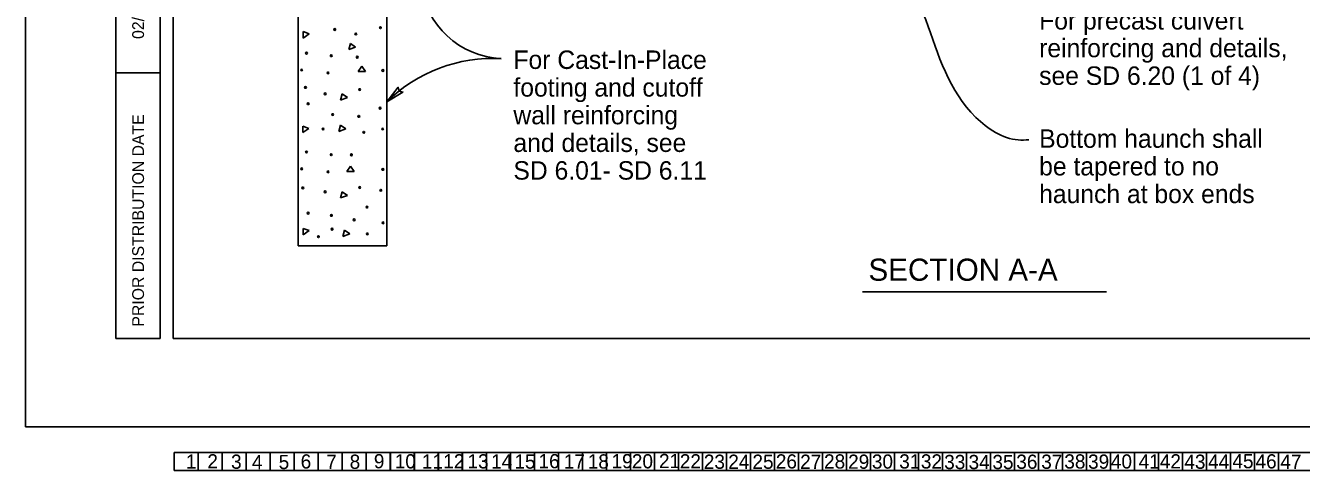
# Model space of a CAD drawing. Extents: x 0 to 2.83, y -0.03 to 1.83.
# Drawn here: x 0 to 0.9, y -0.031 to 0.283 of the extents above; entities that cross this region are included whole.
import ezdxf

# ---------------------------------------------------------------- set-up
doc = ezdxf.new("R2010")
doc.units = 0
for name, color, linetype in [('1', 7, 'Continuous'), ('10', 7, 'Continuous'), ('11', 7, 'Continuous'), ('12', 7, 'Continuous'), ('13', 7, 'Continuous'), ('14', 7, 'Continuous'), ('15', 7, 'Continuous'), ('16', 7, 'Continuous'), ('17', 7, 'Continuous'), ('18', 7, 'Continuous'), ('19', 7, 'Continuous'), ('2', 7, 'Continuous'), ('20', 7, 'Continuous'), ('21', 7, 'Continuous'), ('22', 7, 'Continuous'), ('23', 7, 'Continuous'), ('24', 7, 'Continuous'), ('25', 7, 'Continuous'), ('26', 7, 'Continuous'), ('27', 7, 'Continuous'), ('28', 7, 'Continuous'), ('29', 7, 'Continuous'), ('3', 7, 'Continuous'), ('30', 7, 'Continuous'), ('31', 7, 'Continuous'), ('32', 7, 'Continuous'), ('33', 7, 'Continuous'), ('34', 7, 'Continuous'), ('35', 7, 'Continuous'), ('36', 7, 'Continuous'), ('37', 7, 'Continuous'), ('38', 7, 'Continuous'), ('39', 7, 'Continuous'), ('4', 7, 'Continuous'), ('40', 7, 'Continuous'), ('41', 7, 'Continuous'), ('42', 7, 'Continuous'), ('43', 7, 'Continuous'), ('44', 7, 'Continuous'), ('45', 7, 'Continuous'), ('46', 7, 'Continuous'), ('47', 7, 'Continuous'), ('5', 7, 'Continuous'), ('50', 7, 'Continuous'), ('54', 7, 'Continuous'), ('55', 7, 'Continuous'), ('57', 7, 'Continuous'), ('6', 7, 'Continuous'), ('62', 7, 'Continuous'), ('63', 7, 'Continuous'), ('7', 7, 'Continuous'), ('8', 7, 'Continuous'), ('9', 7, 'Continuous')]:
    doc.layers.add(name, color=color, linetype=linetype)

msp = doc.modelspace()

# ---------------------------------------------------------------- linework, layer by layer
at = {"layer": '50'}
for p, q in [((0.19238, 0.1279), (0.19238, 0.37139)), ((0.25488, 0.1279), (0.25488, 0.31279)), ((0.19589, 0.2745), (0.19587, 0.27906)), ((0.19587, 0.27906), (0.20015, 0.27749)), ((0.20015, 0.27749), (0.19589, 0.2745)), ((0.22799, 0.26628), (0.22915, 0.27068)), ((0.22915, 0.27068), (0.23289, 0.26805)), ((0.23289, 0.26805), (0.22799, 0.26628)), ((0.23462, 0.25087), (0.23722, 0.25461)), ((0.23722, 0.25461), (0.23983, 0.25087)), ((0.23983, 0.25087), (0.23462, 0.25087)), ((0.2223, 0.23071), (0.22347, 0.23511)), ((0.22347, 0.23511), (0.2272, 0.23248)), ((0.2272, 0.23248), (0.2223, 0.23071)), ((0.19563, 0.20772), (0.19562, 0.21228)), ((0.19562, 0.21228), (0.1999, 0.21071)), ((0.1999, 0.21071), (0.19563, 0.20772)), ((0.22096, 0.2085), (0.22213, 0.2129)), ((0.22586, 0.21028), (0.22096, 0.2085)), ((0.22213, 0.2129), (0.22586, 0.21028)), ((0.22666, 0.18037), (0.22926, 0.18412)), ((0.23187, 0.18037), (0.22666, 0.18037)), ((0.22926, 0.18412), (0.23187, 0.18037)), ((0.2223, 0.16156), (0.22347, 0.16596)), ((0.2272, 0.16334), (0.2223, 0.16156)), ((0.22347, 0.16596), (0.2272, 0.16334)), ((0.19589, 0.13555), (0.19587, 0.14011)), ((0.19587, 0.14011), (0.20015, 0.13853)), ((0.20015, 0.13853), (0.19589, 0.13555)), ((0.22384, 0.13442), (0.22501, 0.13882)), ((0.22874, 0.13619), (0.22384, 0.13442)), ((0.22501, 0.13882), (0.22874, 0.13619)), ((0.19238, 0.1279), (0.25488, 0.1279))]:
    msp.add_line(p, q, dxfattribs=at)
for centre in [(0.21815, 0.28053), (0.25037, 0.28178), (0.23299, 0.27734), (0.19824, 0.26382), (0.21569, 0.26196), (0.23404, 0.26094), (0.19479, 0.25193), (0.2521, 0.25155), (0.21337, 0.24986), (0.19748, 0.23961), (0.21136, 0.2351), (0.23572, 0.2381), (0.1994, 0.2281), (0.25014, 0.22501), (0.21668, 0.22044), (0.23512, 0.21918), (0.20991, 0.21025), (0.23864, 0.20791), (0.25196, 0.21029), (0.19824, 0.19401), (0.21569, 0.19215), (0.2299, 0.19201), (0.19479, 0.18212), (0.21337, 0.18004), (0.2521, 0.18174), (0.1956, 0.16869), (0.21136, 0.16595), (0.23572, 0.16896), (0.25065, 0.16699), (0.24092, 0.15517), (0.1994, 0.15088), (0.21578, 0.14926), (0.23184, 0.14618), (0.25217, 0.14403), (0.21628, 0.13957), (0.24114, 0.13618), (0.20662, 0.13428)]:
    msp.add_circle(centre, 0.000626, dxfattribs=at)
at = {"layer": '54'}
msp.add_lwpolyline([(0.25488, 0.22946), (0.26618, 0.2363), (0.26347, 0.23707), (0.2629, 0.23977)], close=True, dxfattribs=at)
at = {"layer": '55'}
for centre, radius, start, end in [((0.33842, 0.31981), 0.05996, 186.7254, 267.33645), ((0.3295, 0.15391), 0.10619, 86.68773, 134.64958)]:
    msp.add_arc(centre, radius, start, end, dxfattribs=at)
msp.add_spline([(0.70782, 0.20258), (0.70033, 0.20258), (0.67037, 0.21846), (0.63506, 0.28728), (0.6158, 0.33281), (0.59119, 0.36775), (0.57514, 0.37939), (0.56016, 0.38469), (0.4949, 0.38786), (0.31393, 0.39457)], degree=3, dxfattribs=at)
at = {"layer": '57'}
msp.add_line((0.59055, 0.09532), (0.76264, 0.09532), dxfattribs=at)
at = {"layer": '62'}
for p, q in [((0.10494, -0.01804), (0.10494, -0.03074)), ((0.10494, -0.01804), (1.17174, -0.01804)), ((0.10496, -0.0181), (0.10496, -0.0308)), ((0.10496, -0.0181), (1.17175, -0.0181)), ((0.12188, -0.01804), (0.12188, -0.03074)), ((0.12189, -0.0181), (0.12189, -0.0308)), ((0.13881, -0.01804), (0.13881, -0.03074)), ((0.13882, -0.0181), (0.13882, -0.0308)), ((0.15574, -0.01804), (0.15574, -0.03074)), ((0.15576, -0.0181), (0.15576, -0.0308)), ((0.17267, -0.01804), (0.17267, -0.03074)), ((0.17269, -0.0181), (0.17269, -0.0308)), ((0.18961, -0.01804), (0.18961, -0.03074)), ((0.18962, -0.0181), (0.18962, -0.0308)), ((0.20654, -0.01804), (0.20654, -0.03074)), ((0.20656, -0.0181), (0.20656, -0.0308)), ((0.22348, -0.01804), (0.22348, -0.03074)), ((0.22349, -0.0181), (0.22349, -0.0308)), ((0.24041, -0.01804), (0.24041, -0.03074)), ((0.24042, -0.0181), (0.24042, -0.0308)), ((0.25734, -0.01804), (0.25734, -0.03074)), ((0.25736, -0.0181), (0.25736, -0.0308)), ((0.27427, -0.01804), (0.27427, -0.03074)), ((0.27429, -0.0181), (0.27429, -0.0308)), ((0.29121, -0.01804), (0.29121, -0.03074)), ((0.29122, -0.0181), (0.29122, -0.0308)), ((0.30814, -0.01804), (0.30814, -0.03074)), ((0.30816, -0.0181), (0.30816, -0.0308)), ((0.32508, -0.01804), (0.32508, -0.03074)), ((0.32509, -0.0181), (0.32509, -0.0308)), ((0.34201, -0.01804), (0.34201, -0.03074)), ((0.34202, -0.0181), (0.34202, -0.0308)), ((0.35894, -0.01804), (0.35894, -0.03074)), ((0.35896, -0.0181), (0.35896, -0.0308)), ((0.37588, -0.01804), (0.37588, -0.03074)), ((0.37589, -0.0181), (0.37589, -0.0308)), ((0.39281, -0.01804), (0.39281, -0.03074)), ((0.39282, -0.0181), (0.39282, -0.0308)), ((0.40974, -0.01804), (0.40974, -0.03074)), ((0.40976, -0.0181), (0.40976, -0.0308)), ((0.42668, -0.01804), (0.42668, -0.03074)), ((0.42669, -0.0181), (0.42669, -0.0308)), ((0.44361, -0.01804), (0.44361, -0.03074)), ((0.44362, -0.0181), (0.44362, -0.0308)), ((0.46054, -0.01804), (0.46054, -0.03074)), ((0.46056, -0.0181), (0.46056, -0.0308)), ((0.47748, -0.01804), (0.47748, -0.03074)), ((0.47749, -0.0181), (0.47749, -0.0308)), ((0.49441, -0.01804), (0.49441, -0.03074)), ((0.49442, -0.0181), (0.49442, -0.0308)), ((0.51134, -0.01804), (0.51134, -0.03074)), ((0.51136, -0.0181), (0.51136, -0.0308)), ((0.52828, -0.01804), (0.52828, -0.03074)), ((0.52829, -0.0181), (0.52829, -0.0308)), ((0.54521, -0.01804), (0.54521, -0.03074)), ((0.54522, -0.0181), (0.54522, -0.0308)), ((0.56214, -0.01804), (0.56214, -0.03074)), ((0.56216, -0.0181), (0.56216, -0.0308)), ((0.57908, -0.01804), (0.57908, -0.03074)), ((0.57909, -0.0181), (0.57909, -0.0308)), ((0.59601, -0.01804), (0.59601, -0.03074)), ((0.59602, -0.0181), (0.59602, -0.0308)), ((0.61294, -0.01804), (0.61294, -0.03074)), ((0.61296, -0.0181), (0.61296, -0.0308)), ((0.62988, -0.01804), (0.62988, -0.03074)), ((0.62989, -0.0181), (0.62989, -0.0308)), ((0.64681, -0.01804), (0.64681, -0.03074)), ((0.64682, -0.0181), (0.64682, -0.0308)), ((0.66374, -0.01804), (0.66374, -0.03074)), ((0.66376, -0.0181), (0.66376, -0.0308)), ((0.68068, -0.01804), (0.68068, -0.03074)), ((0.68069, -0.0181), (0.68069, -0.0308)), ((0.69761, -0.01804), (0.69761, -0.03074)), ((0.69762, -0.0181), (0.69762, -0.0308)), ((0.71454, -0.01804), (0.71454, -0.03074)), ((0.71456, -0.0181), (0.71456, -0.0308)), ((0.73147, -0.01804), (0.73147, -0.03074)), ((0.73149, -0.0181), (0.73149, -0.0308)), ((0.74841, -0.01804), (0.74841, -0.03074)), ((0.74842, -0.0181), (0.74842, -0.0308)), ((0.76534, -0.01804), (0.76534, -0.03074)), ((0.76536, -0.0181), (0.76536, -0.0308)), ((0.78228, -0.01804), (0.78228, -0.03074)), ((0.78229, -0.0181), (0.78229, -0.0308)), ((0.79921, -0.01804), (0.79921, -0.03074)), ((0.79922, -0.0181), (0.79922, -0.0308)), ((0.81614, -0.01804), (0.81614, -0.03074)), ((0.81616, -0.0181), (0.81616, -0.0308)), ((0.83308, -0.01804), (0.83308, -0.03074)), ((0.83309, -0.0181), (0.83309, -0.0308)), ((0.85001, -0.01804), (0.85001, -0.03074)), ((0.85002, -0.0181), (0.85002, -0.0308)), ((0.86694, -0.01804), (0.86694, -0.03074)), ((0.86695, -0.0181), (0.86695, -0.0308)), ((0.88388, -0.01804), (0.88388, -0.03074)), ((0.88389, -0.0181), (0.88389, -0.0308)), ((0.10494, -0.03074), (1.17174, -0.03074)), ((0.10496, -0.0308), (1.17175, -0.0308))]:
    msp.add_line(p, q, dxfattribs=at)
at = {"layer": '63'}
for p, q in [((0, 0), (0, 1.83333)), ((0.06381, 0.06244), (0.06381, 0.33328)), ((0.09506, 0.06244), (0.09506, 0.33328)), ((0.09506, 0.24994), (0.06381, 0.24994)), ((0.09506, 0.06244), (0.06381, 0.06244)), ((2.83333, 0), (0, 0))]:
    msp.add_line(p, q, dxfattribs=at)
msp.add_lwpolyline([(2.72918, 1.77077), (0.10418, 1.77077), (0.10418, 0.06244), (2.72918, 0.06244)], close=True, dxfattribs=at)

# ---------------------------------------------------------------- texts
at = {"layer": '1'}
for p in [(0.11316, -0.02944), (0.11317, -0.02949)]:
    msp.add_text('1', height=0.01, rotation=360, dxfattribs=at).set_placement(p)
at = {"layer": '10'}
for p in [(0.26046, -0.02928), (0.26047, -0.02934)]:
    msp.add_text('10', height=0.01, rotation=360, dxfattribs=at).set_placement(p)
at = {"layer": '11'}
for p in [(0.2796, -0.02937), (0.27961, -0.02942)]:
    msp.add_text('11', height=0.01, rotation=360, dxfattribs=at).set_placement(p)
at = {"layer": '12'}
for p in [(0.29469, -0.02925), (0.29471, -0.0293)]:
    msp.add_text('12', height=0.01, rotation=360, dxfattribs=at).set_placement(p)
at = {"layer": '13'}
for p in [(0.31181, -0.02928), (0.31182, -0.02933)]:
    msp.add_text('13', height=0.01, rotation=360, dxfattribs=at).set_placement(p)
at = {"layer": '14'}
for p in [(0.32844, -0.02939), (0.32846, -0.02944)]:
    msp.add_text('14', height=0.01, rotation=360, dxfattribs=at).set_placement(p)
at = {"layer": '15'}
for p in [(0.34488, -0.02946), (0.34489, -0.02951)]:
    msp.add_text('15', height=0.01, rotation=360, dxfattribs=at).set_placement(p)
at = {"layer": '16'}
for p in [(0.3619, -0.02918), (0.36191, -0.02923)]:
    msp.add_text('16', height=0.01, rotation=360, dxfattribs=at).set_placement(p)
at = {"layer": '17'}
for p in [(0.3797, -0.02946), (0.37971, -0.02951)]:
    msp.add_text('17', height=0.01, rotation=360, dxfattribs=at).set_placement(p)
at = {"layer": '18'}
for p in [(0.39663, -0.02938), (0.39664, -0.02943)]:
    msp.add_text('18', height=0.01, rotation=360, dxfattribs=at).set_placement(p)
at = {"layer": '19'}
for p in [(0.4134, -0.02918), (0.41342, -0.02923)]:
    msp.add_text('19', height=0.01, rotation=360, dxfattribs=at).set_placement(p)
at = {"layer": '2'}
for p in [(0.12828, -0.02928), (0.12829, -0.02934)]:
    msp.add_text('2', height=0.01, rotation=360, dxfattribs=at).set_placement(p)
at = {"layer": '20'}
for p in [(0.42774, -0.02926), (0.42776, -0.02931)]:
    msp.add_text('20', height=0.01, rotation=360, dxfattribs=at).set_placement(p)
at = {"layer": '21'}
for p in [(0.44688, -0.02909), (0.44689, -0.02914)]:
    msp.add_text('21', height=0.01, rotation=360, dxfattribs=at).set_placement(p)
at = {"layer": '22'}
for p in [(0.46158, -0.02929), (0.46159, -0.02934)]:
    msp.add_text('22', height=0.01, rotation=360, dxfattribs=at).set_placement(p)
at = {"layer": '23'}
for p in [(0.47852, -0.02958), (0.47853, -0.02963)]:
    msp.add_text('23', height=0.01, rotation=360, dxfattribs=at).set_placement(p)
at = {"layer": '24'}
for p in [(0.49576, -0.02958), (0.49577, -0.02963)]:
    msp.add_text('24', height=0.01, rotation=360, dxfattribs=at).set_placement(p)
at = {"layer": '25'}
for p in [(0.51281, -0.02958), (0.51282, -0.02963)]:
    msp.add_text('25', height=0.01, rotation=360, dxfattribs=at).set_placement(p)
at = {"layer": '26'}
for p in [(0.52931, -0.02936), (0.52932, -0.02941)]:
    msp.add_text('26', height=0.01, rotation=360, dxfattribs=at).set_placement(p)
at = {"layer": '27'}
for p in [(0.54648, -0.02958), (0.54649, -0.02963)]:
    msp.add_text('27', height=0.01, rotation=360, dxfattribs=at).set_placement(p)
at = {"layer": '28'}
for p in [(0.56333, -0.02938), (0.56334, -0.02943)]:
    msp.add_text('28', height=0.01, rotation=360, dxfattribs=at).set_placement(p)
at = {"layer": '29'}
for p in [(0.58032, -0.02956), (0.58034, -0.02961)]:
    msp.add_text('29', height=0.01, rotation=360, dxfattribs=at).set_placement(p)
at = {"layer": '3'}
for p in [(0.145, -0.02955), (0.14501, -0.02961)]:
    msp.add_text('3', height=0.01, rotation=360, dxfattribs=at).set_placement(p)
at = {"layer": '30'}
for p in [(0.59706, -0.02946), (0.59707, -0.02951)]:
    msp.add_text('30', height=0.01, rotation=360, dxfattribs=at).set_placement(p)
at = {"layer": '31'}
for p in [(0.61636, -0.02938), (0.61637, -0.02943)]:
    msp.add_text('31', height=0.01, rotation=360, dxfattribs=at).set_placement(p)
at = {"layer": '32'}
for p in [(0.63163, -0.02938), (0.63165, -0.02943)]:
    msp.add_text('32', height=0.01, rotation=360, dxfattribs=at).set_placement(p)
at = {"layer": '33'}
for p in [(0.64808, -0.02978), (0.64809, -0.02983)]:
    msp.add_text('33', height=0.01, rotation=360, dxfattribs=at).set_placement(p)
at = {"layer": '34'}
for p in [(0.66527, -0.02978), (0.66528, -0.02984)]:
    msp.add_text('34', height=0.01, rotation=360, dxfattribs=at).set_placement(p)
at = {"layer": '35'}
for p in [(0.68209, -0.02978), (0.68211, -0.02984)]:
    msp.add_text('35', height=0.01, rotation=360, dxfattribs=at).set_placement(p)
at = {"layer": '36'}
for p in [(0.69895, -0.02958), (0.69896, -0.02964)]:
    msp.add_text('36', height=0.01, rotation=360, dxfattribs=at).set_placement(p)
at = {"layer": '37'}
for p in [(0.71654, -0.02958), (0.71655, -0.02964)]:
    msp.add_text('37', height=0.01, rotation=360, dxfattribs=at).set_placement(p)
at = {"layer": '38'}
for p in [(0.73281, -0.02938), (0.73282, -0.02943)]:
    msp.add_text('38', height=0.01, rotation=360, dxfattribs=at).set_placement(p)
at = {"layer": '39'}
for p in [(0.74958, -0.0295), (0.74959, -0.02955)]:
    msp.add_text('39', height=0.01, rotation=360, dxfattribs=at).set_placement(p)
at = {"layer": '4'}
for p in [(0.15973, -0.02984), (0.15975, -0.0299)]:
    msp.add_text('4', height=0.01, rotation=360, dxfattribs=at).set_placement(p)
at = {"layer": '40'}
for p in [(0.76566, -0.02938), (0.76567, -0.02944)]:
    msp.add_text('40', height=0.01, rotation=360, dxfattribs=at).set_placement(p)
at = {"layer": '41'}
for p in [(0.78528, -0.02938), (0.7853, -0.02943)]:
    msp.add_text('41', height=0.01, rotation=360, dxfattribs=at).set_placement(p)
at = {"layer": '42'}
for p in [(0.8002, -0.0293), (0.80022, -0.02936)]:
    msp.add_text('42', height=0.01, rotation=360, dxfattribs=at).set_placement(p)
at = {"layer": '43'}
for p in [(0.8175, -0.02958), (0.81751, -0.02964)]:
    msp.add_text('43', height=0.01, rotation=360, dxfattribs=at).set_placement(p)
at = {"layer": '44'}
for p in [(0.83425, -0.02949), (0.83427, -0.02955)]:
    msp.add_text('44', height=0.01, rotation=360, dxfattribs=at).set_placement(p)
at = {"layer": '45'}
for p in [(0.85139, -0.02918), (0.8514, -0.02924)]:
    msp.add_text('45', height=0.01, rotation=360, dxfattribs=at).set_placement(p)
at = {"layer": '46'}
for p in [(0.8677, -0.02929), (0.86771, -0.02935)]:
    msp.add_text('46', height=0.01, rotation=360, dxfattribs=at).set_placement(p)
at = {"layer": '47'}
for p in [(0.8852, -0.02958), (0.88522, -0.02964)]:
    msp.add_text('47', height=0.01, rotation=360, dxfattribs=at).set_placement(p)
at = {"layer": '5'}
for p in [(0.17858, -0.02977), (0.17859, -0.02982)]:
    msp.add_text('5', height=0.01, rotation=360, dxfattribs=at).set_placement(p)
at = {"layer": '57'}
for s, height, p in [('For precast culvert', 0.0130208, (0.71506, 0.28046)), ('reinforcing and details,', 0.0130208, (0.71506, 0.26093)), ('For Cast-In-Place ', 0.0130208, (0.34418, 0.25266)), ('see SD 6.20 (1 of 4)', 0.0130208, (0.71506, 0.2414)), ('footing and cutoff ', 0.0130208, (0.34418, 0.23313)), ('wall reinforcing', 0.0130208, (0.34418, 0.21359)), ('and details, see ', 0.0130208, (0.34418, 0.19406)), ('Bottom haunch shall ', 0.0130208, (0.71506, 0.19701)), ('be tapered to no', 0.0130208, (0.71506, 0.17748)), ('SD 6.01- SD 6.11', 0.0130208, (0.34418, 0.17453)), ('haunch at box ends', 0.0130208, (0.71506, 0.15794)), ('SECTION A-A', 0.015625, (0.59464, 0.10313))]:
    msp.add_text(s, height=height, dxfattribs=at).set_placement(p)
at = {"layer": '6'}
for p in [(0.19409, -0.02938), (0.19411, -0.02943)]:
    msp.add_text('6', height=0.01, rotation=360, dxfattribs=at).set_placement(p)
at = {"layer": '63'}
for s, height, p in [('02/23', 0.008333, (0.0836, 0.27384)), ('PRIOR DISTRIBUTION DATE', 0.0083333, (0.0836, 0.07078))]:
    msp.add_text(s, height=height, rotation=90, dxfattribs=at).set_placement(p)
at = {"layer": '7'}
for p in [(0.21211, -0.02964), (0.21212, -0.02969)]:
    msp.add_text('7', height=0.01, rotation=360, dxfattribs=at).set_placement(p)
at = {"layer": '8'}
for p in [(0.22865, -0.02958), (0.22866, -0.02963)]:
    msp.add_text('8', height=0.01, rotation=360, dxfattribs=at).set_placement(p)
at = {"layer": '9'}
for p in [(0.24573, -0.02921), (0.24574, -0.02926)]:
    msp.add_text('9', height=0.01, rotation=360, dxfattribs=at).set_placement(p)

doc.saveas('drawing.dxf')
